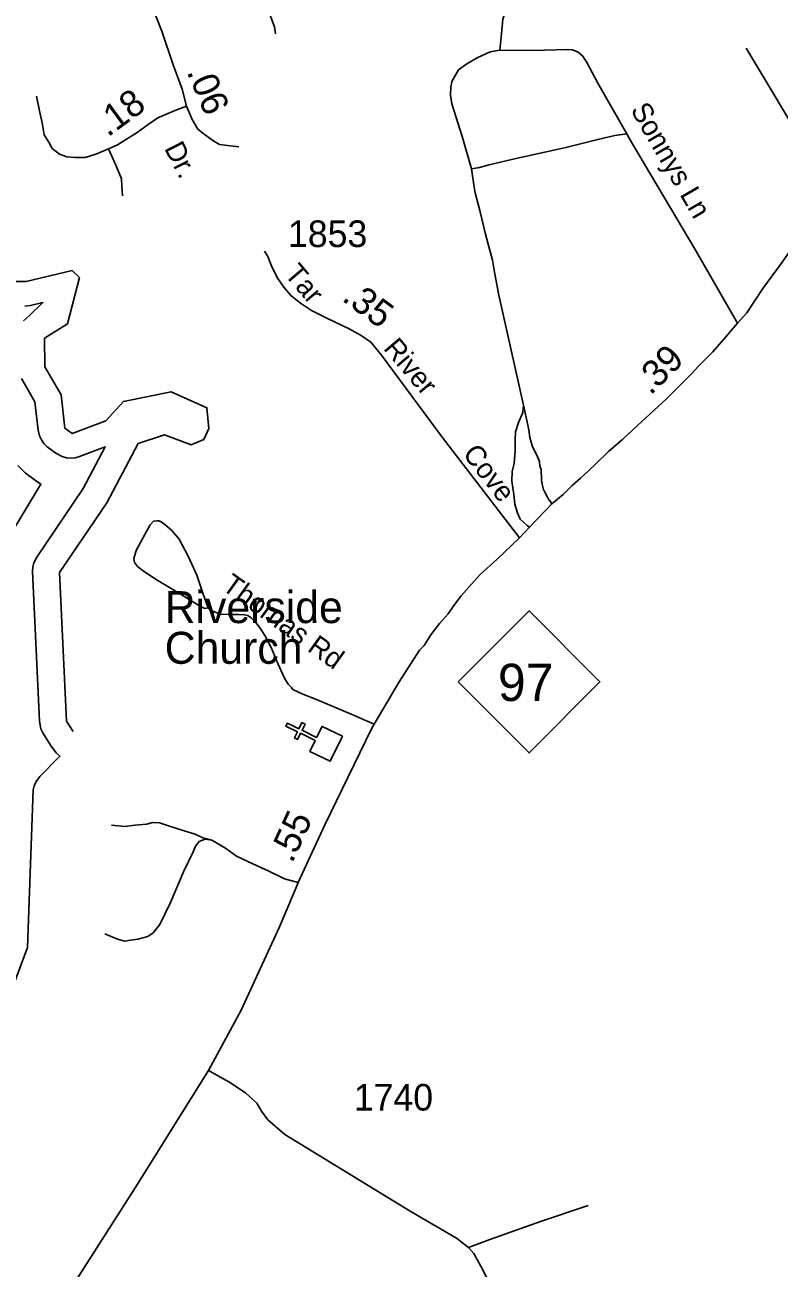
# Model space of a CAD drawing. Extents: x 2220236 to 2384410, y 720751 to 894131.
# Drawn here: x 2329583 to 2333123, y 772786 to 778623 of the extents above; entities that cross this region are included whole.
import ezdxf

# ---------------------------------------------------------------- set-up
doc = ezdxf.new("R2010")
doc.units = 0
doc.layers.add('Default', color=7, linetype='Continuous')

msp = doc.modelspace()

# ---------------------------------------------------------------- linework, layer by layer
at = {"layer": 'Default'}
msp.add_line((2332045, 776391), (2332056.4, 776374.2), dxfattribs=at)
for points in [[(2329831.5, 779523.6), (2329908.2, 779341), (2330030.6, 779050.7), (2330155.7, 778773.7), (2330224.9, 778592.6), (2330278.1, 778435.5), (2330320.7, 778321), (2330342, 778241.1)], [(2331621.1, 779429), (2331621.7, 779385.3), (2331631.4, 779241.3), (2331631.8, 779207.3), (2331636.4, 779153.3), (2331655.3, 779061.6), (2331665.6, 779045.6), (2331684, 779002), (2331696.2, 778982.1), (2331757.5, 778862.7), (2331779.8, 778825), (2331813.4, 778776.6), (2331825.7, 778746.7), (2331833.8, 778726.3), (2331837.9, 778704.5), (2331836.5, 778682.7), (2331825.7, 778648.7), (2331820.2, 778580.7), (2331816.1, 778550.8), (2331812.1, 778503.9)], [(2330592.8, 779021.5), (2330659.9, 778854.3), (2330715.1, 778717.3), (2330754.7, 778613.9), (2330759.8, 778581.1)], [(2331812.1, 778503.9), (2331767.2, 778495.7), (2331706, 778468.5), (2331657.1, 778439.9), (2331618.5, 778411.5), (2331586.4, 778357), (2331585, 778346.1), (2331582.3, 778333.8), (2331581, 778293), (2331586.4, 778252.2), (2331636.7, 778094.4), (2331679.1, 777947.5)], [(2332408.1, 778110.8), (2332271.5, 778348.8), (2332218.5, 778449.5), (2332199.5, 778476.7), (2332180.5, 778494.4), (2332153.3, 778505.2), (2332131.5, 778506.6), (2332077.1, 778505.2), (2331967, 778502.5), (2331812.1, 778503.9)], [(2333591, 778165.2), (2333561.3, 778182.7), (2333543.7, 778189.3), (2333537.1, 778188.2), (2333527.3, 778181.6), (2333431.2, 778025.1), (2333403.7, 777977.8), (2333374.1, 777942.7), (2333356.6, 777930.5), (2333348.8, 777925.1), (2333338.9, 777926.2), (2333325.8, 777920.7), (2333314.8, 777930.6), (2333294.4, 777965.8), (2333270, 778009.4), (2332968.7, 778513.9)], [(2330342, 778241.1), (2330283.4, 778218.5), (2330206.3, 778186.5), (2330161, 778154.6), (2330110.5, 778117.3), (2330059.9, 778085.3), (2330017.3, 778058.7), (2329974.7, 778040), (2329916.2, 778016.1), (2329865.6, 778000.1), (2329817.7, 778000.1), (2329780.4, 778002.8), (2329745.9, 778016.1), (2329711.3, 778042.7), (2329695.3, 778072), (2329674, 778106.6), (2329663.3, 778162.5), (2329652.7, 778210.5), (2329636.7, 778287.7)], [(2330342, 778241.1), (2330368.6, 778178.5), (2330395.2, 778133.3), (2330424.5, 778109.3), (2330464.4, 778080), (2330496.4, 778061.4), (2330533.6, 778056), (2330586.8, 778050.7)], [(2332408.1, 778110.8), (2332352, 778104), (2332271.8, 778084.9), (2332122.3, 778046.8), (2332023, 778025.1), (2331881.7, 777993.8), (2331762, 777965.2), (2331717.2, 777953), (2331679.1, 777947.5)], [(2332928.1, 777222.5), (2332728.3, 777568), (2332431.9, 778069.3), (2332408.1, 778110.8)], [(2329974.7, 778040), (2330009.3, 777964.1), (2330035.9, 777900.2), (2330038.6, 777865.6), (2330041.3, 777820.3)], [(2331679.1, 777947.5), (2331692.4, 777860.4), (2331696.7, 777834.5), (2331718.3, 777751.7), (2331744.1, 777640.1), (2331778, 777517.5), (2331786.5, 777461.7), (2331807.7, 777354.1), (2331922.6, 776837.4)], [(2331904.1, 776214), (2331951.3, 776263.7), (2332056.4, 776374.2), (2332109.8, 776417.3), (2332151.9, 776460.8), (2332191.3, 776494.8), (2332228, 776528.8), (2332263.4, 776561.4), (2332324.5, 776621.3), (2332388.4, 776675.7), (2332460.5, 776743), (2332592.3, 776865.5), (2332660.3, 776932.1), (2332690.2, 776962), (2332713.3, 776986.5), (2332744.6, 777020.5), (2332811.2, 777087.9), (2332864.2, 777146.4), (2332928.1, 777222.5), (2332970.8, 777271.1), (2333046.3, 777384.3), (2333129.6, 777498.1), (2333298.9, 777737.9)], [(2331904.1, 776214), (2331540.7, 776686.6), (2331256.4, 777071.9), (2331206, 777132.2), (2331161, 777164.6), (2331105.3, 777195.2), (2331002.7, 777243.8), (2330928.9, 777281.6), (2330876.8, 777315.9), (2330831.8, 777351.9), (2330797.6, 777391.5), (2330770.6, 777431.1), (2330741.8, 777486.9), (2330723.8, 777535.5), (2330707.6, 777560.7)], [(2329808.9, 775304.6), (2329778, 775354), (2329745, 776051.7), (2329967, 776379.1), (2330114.1, 776657.5), (2330238.1, 776698.7), (2330364, 776651.3), (2330422.1, 776676.7), (2330446.1, 776726.9), (2330437, 776825), (2330269.1, 776900.2), (2330045, 776854.9), (2329962.9, 776762.9), (2329805.1, 776704), (2329771, 776728.9), (2329753, 776885.7), (2329677.1, 777017.1), (2329675, 777151.7), (2329783.1, 777218.4), (2329839.1, 777437.2), (2329805.1, 777468.7), (2329589.1, 777417.2), (2329506.1, 777417.1)], [(2329582.4, 777302.1), (2329609.8, 777305.4), (2329667.3, 777319.1), (2329605.1, 777258.6), (2329576, 777233.7)], [(2329566.2, 776962), (2329629.7, 776852.1), (2329644.9, 776720.1), (2329651.3, 776692.7), (2329660.1, 776673.8), (2329672, 776656.7), (2329686.7, 776641.8), (2329727.3, 776612.1), (2329757.1, 776596.2), (2329777.4, 776590.7), (2329798.1, 776588.9), (2329818.8, 776590.7), (2329839.1, 776596.2), (2329960.3, 776641.4), (2329857.1, 776445.9), (2329638.8, 776124), (2329625.2, 776097.7), (2329619.9, 776077.5), (2329618, 776056.7), (2329651.3, 775353.2), (2329658.2, 775317.9), (2329667.1, 775298.9), (2329703.3, 775240.9), (2329729.6, 775205.6), (2329747.2, 775189.9), (2329653.5, 775094), (2329635.1, 775069.8), (2329626.2, 775050.8), (2329620.9, 775030.6), (2329594.9, 774290.9), (2329450.5, 773909.9)], [(2331922.6, 776837.4), (2331920.1, 776803.3), (2331900.4, 776756.5), (2331886.1, 776712.7), (2331884.3, 776673.1), (2331884.3, 776620.9), (2331878.9, 776563.3), (2331869.9, 776525.5), (2331868.1, 776480.5), (2331877.1, 776417.5), (2331882.5, 776372.5), (2331893.3, 776334.7), (2331907.7, 776302.3), (2331923.9, 776287.9), (2331940.1, 776271.6), (2331951.3, 776263.7)], [(2331922.6, 776837.4), (2331948.3, 776721.8), (2331952.8, 776685.8), (2331965.2, 776642.1), (2331971.3, 776630.1), (2331989.7, 776595), (2331998.1, 776572.4), (2332000.2, 776550.5), (2332006.4, 776534.5), (2332007, 776486.6), (2332011.2, 776466.5), (2332017.8, 776440.8), (2332025.9, 776422.7), (2332035.9, 776405.5), (2332043.5, 776390.2)], [(2329549.6, 776553.8), (2329584, 776519.3), (2329632.8, 776482.9), (2329658, 776466.4), (2329506.3, 776213.8)], [(2330443.2, 775885.5), (2330419.8, 775950.3), (2330389.2, 776038.5), (2330349.6, 776128.5), (2330306.4, 776207.7), (2330272.2, 776249.1), (2330241.6, 776276.1), (2330221.9, 776288.8), (2330211.1, 776294.2), (2330202.1, 776294.2), (2330185.9, 776292.4), (2330171.5, 776276.1), (2330148.1, 776232.9), (2330104.9, 776155.5), (2330094.1, 776117.7), (2330097.7, 776097.9), (2330112.1, 776079.9), (2330144.5, 776054.7), (2330198.5, 776018.7), (2330301, 775957.5), (2330394.6, 775899.9), (2330427, 775881.9), (2330443.2, 775885.5)], [(2330445.1, 773713.1), (2330598, 773996.7), (2330777.7, 774388.5), (2330855.8, 774573.1), (2330866.3, 774595.9), (2330990.5, 774866.4), (2331209.8, 775318.4), (2331222.1, 775339.2), (2331339.5, 775537.8), (2331435.8, 775686.8), (2331457.5, 775709.1), (2331488.9, 775759.4), (2331528.4, 775811.6), (2331569.9, 775858.1), (2331595.5, 775896.4), (2331630.8, 775942.8), (2331691.8, 776010.6), (2331719.8, 776041.7), (2331799.8, 776115), (2331904.1, 776214)], [(2331222.1, 775339.2), (2331114.3, 775386.8), (2330952.3, 775455.2), (2330887.6, 775480.4), (2330864.2, 775491.2), (2330840.8, 775502), (2330833.6, 775511), (2330819.2, 775527.2), (2330801.2, 775556), (2330770.6, 775624.4), (2330738.2, 775700), (2330709.4, 775755.8), (2330687.8, 775790.1), (2330664.5, 775818.9), (2330644.7, 775838.7), (2330628.5, 775849.5), (2330614.1, 775853.1), (2330587.1, 775854.9), (2330560.1, 775854.9), (2330536.7, 775854.9), (2330502.5, 775856.7), (2330475.5, 775865.7), (2330455.8, 775874.7), (2330443.2, 775885.5)], [(2329989.7, 774865.8), (2330053.8, 774858.4), (2330098.2, 774865.8), (2330154.9, 774870.8), (2330182, 774878.2), (2330214.1, 774875.7), (2330260.9, 774860.9), (2330330, 774838.7), (2330381.8, 774823.9), (2330418.7, 774806.6), (2330460.7, 774794.3)], [(2329957.6, 774355.1), (2330016.8, 774330.4), (2330051.3, 774320.5), (2330078.4, 774325.5), (2330113, 774330.4), (2330159.8, 774342.7), (2330184.5, 774360), (2330216.5, 774399.5), (2330265.9, 774503.1), (2330327.5, 774646.2), (2330371.9, 774740), (2330384.2, 774767.1), (2330401.5, 774789.4), (2330416.3, 774794.3), (2330428.6, 774799.2), (2330460.7, 774794.3)], [(2330460.7, 774794.3), (2330524.8, 774757.3), (2330576.6, 774720.3), (2330653, 774683.3), (2330724.5, 774651.2), (2330801, 774614.2), (2330866.3, 774595.9)], [(2328690.1, 770945.4), (2328784.2, 771092.5), (2329297.2, 771901.7), (2329499.8, 772217.6), (2329668.8, 772487.4), (2330111.2, 773179.8), (2330402, 773646.8), (2330445.1, 773713.1)], [(2330445.1, 773713.1), (2330539.7, 773660.2), (2330618.2, 773609), (2330670.9, 773559.7), (2330693.2, 773522), (2330723.6, 773482.2), (2330802.3, 773413.2), (2331391.9, 773053.7), (2331609.1, 772926.1), (2331665.5, 772882.6), (2331689.9, 772855), (2331724.5, 772791.4), (2331800.1, 772644.2), (2331845.1, 772550.9), (2331873.9, 772473.2), (2331888.6, 772417.4), (2331888.9, 772389.4), (2331885.1, 772365.2), (2331869.5, 772325.2), (2331832.2, 772262.9), (2331513.6, 771775.5), (2331338.6, 771499.9), (2331126.3, 771169.8), (2330896.9, 770816.4)], [(2332227.2, 773080.6), (2332008.2, 773006.2), (2331765.1, 772919.7), (2331665.5, 772882.6)]]:
    msp.add_lwpolyline(points, dxfattribs=at)
for points in [[(2331616.1, 775538), (2331949.1, 775871), (2332282.1, 775538), (2331949.1, 775205)], [(2330920.2, 775211.9), (2330945.1, 775263.2), (2330876.7, 775296.6), (2330862.6, 775267.8), (2330848.3, 775274.8), (2330862.3, 775303.6), (2330808.3, 775329.9), (2330815.3, 775344.4), (2330869.4, 775318), (2330883.4, 775346.7), (2330897.8, 775339.7), (2330883.7, 775311), (2330952.1, 775277.6), (2330977.5, 775329.3), (2331073.2, 775282.6), (2331015.9, 775165.2)]]:
    msp.add_lwpolyline(points, close=True, dxfattribs=at)

# ---------------------------------------------------------------- texts
for s, height, rotation, p in [('.06', 125, 293.03853, (2330341, 778402.5)), ('.18', 125, 36.40163, (2329972.2, 778093)), ('Sonnys Ln', 95, 300.23968, (2332423.4, 778223.6)), ('Dr.', 95, 297.16667, (2330235.3, 778043.7)), ('Tar', 95, 310.48949, (2330797.3, 777450.4)), ('.35', 125, 323.33284, (2331065.9, 777331.5)), ('River', 95, 310.33196, (2331262.2, 777102.1)), ('.39', 125, 45.01807, (2332519.9, 776880.1)), ('Cove', 95, 307.73472, (2331634.2, 776608.2)), ('Thomas Rd', 95, 324.29459, (2330502.3, 775975.3)), ('.55', 125, 65.33975, (2330837.7, 774683.3))]:
    msp.add_text(s, height=height, rotation=rotation, dxfattribs=at).set_placement(p)
for s, height, p in [('1853', 125, (2330817.9, 777579.5)), ('Riverside', 150, (2330239, 775814.1)), ('Church', 150, (2330239, 775623.1)), ('97', 175, (2331803.3, 775448.3)), ('1740', 125, (2331126.9, 773525.6))]:
    msp.add_text(s, height=height, dxfattribs=at).set_placement(p)

doc.saveas('drawing.dxf')
